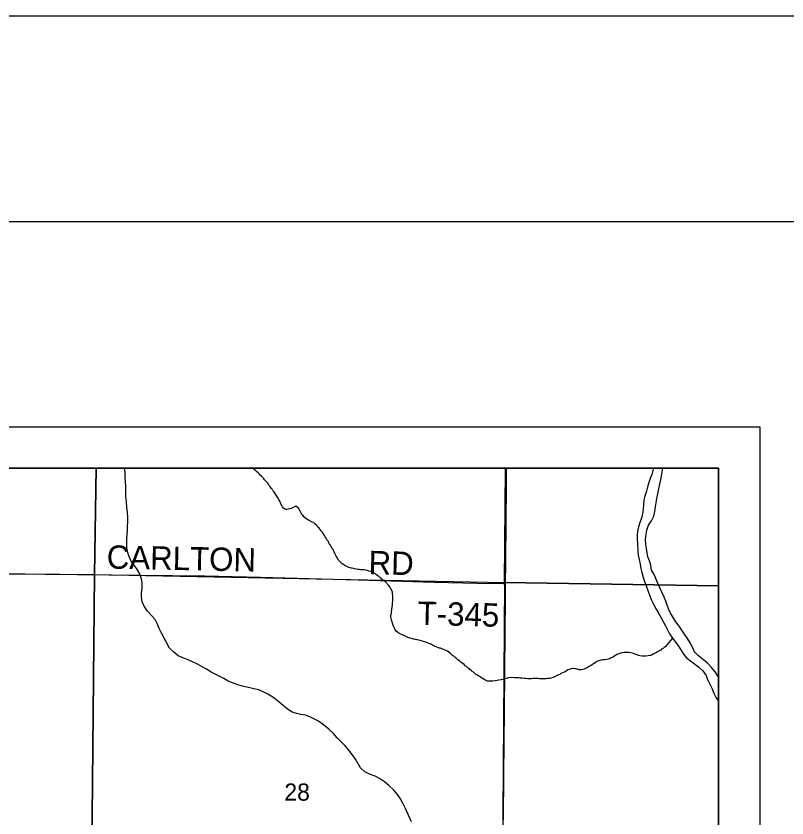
# Model space of a CAD drawing. Extents: x -8.8 to 41.4, y 0 to 34.6.
# Drawn here: x 7.191 to 9.066, y 20.049 to 22 of the extents above; entities that cross this region are included whole.
import ezdxf

# ---------------------------------------------------------------- set-up
doc = ezdxf.new("R2010")
doc.units = 0
for name, color, linetype in [('GM_X_Corporation', 7, 'Continuous'), ('GM_X_Major_Lake', 7, 'Continuous'), ('GM_X_Minor_River', 7, 'Continuous'), ('GM_X_Section_Text', 7, 'Continuous'), ('GM_X_State_Route', 7, 'Continuous'), ('GM_X_Township_Road', 7, 'Continuous'), ('GM_X_Township_Text', 7, 'Continuous'), ('SH_Border', 7, 'Continuous'), ('SH_Cut_Line', 7, 'Continuous'), ('SH_Text', 7, 'Continuous')]:
    doc.layers.add(name, color=color, linetype=linetype)

msp = doc.modelspace()

# ---------------------------------------------------------------- linework, layer by layer
at = {"layer": 'GM_X_Corporation'}
msp.add_lwpolyline([(8.9, 18.5906), (8.9, 20.9), (5.406, 20.9), (5.4056, 20.8652), (5.4051, 20.8193), (5.404, 20.7626), (5.4029, 20.685), (5.4022, 20.6229), (5.4014, 20.5837), (5.4004, 20.5036), (5.3996, 20.4046), (5.3985, 20.3439), (5.3972, 20.2756), (5.3969, 20.2195), (5.3955, 20.1339), (5.3942, 20.0451)], dxfattribs=at)
for points in [[(7.3859, 20.9), (6.3738, 20.9), (6.3701, 20.6506), (7.3817, 20.6407)], [(8.3813, 20.9), (7.3859, 20.9), (7.3817, 20.6407), (8.3787, 20.6214)], [(8.9, 20.6135), (8.9, 20.9), (8.3813, 20.9), (8.3787, 20.6214)], [(6.3701, 20.6506), (7.3817, 20.6407), (7.3719, 19.6303), (6.3565, 19.6406)], [(7.3817, 20.6407), (8.3787, 20.6214), (8.3714, 19.6082), (7.3719, 19.6303)], [(8.9, 19.5991), (8.9, 20.6135), (8.3787, 20.6214), (8.3714, 19.6082)]]:
    msp.add_lwpolyline(points, close=True, dxfattribs=at)
at = {"layer": 'GM_X_Major_Lake'}
for points in [[(8.7418, 20.9), (8.741, 20.8976), (8.7378, 20.8847), (8.7338, 20.8746), (8.7302, 20.8648), (8.7266, 20.8538), (8.7241, 20.8436), (8.7205, 20.8319), (8.7184, 20.8221), (8.717, 20.8111), (8.7165, 20.8004), (8.7144, 20.7887), (8.7123, 20.7785), (8.7079, 20.7679), (8.7047, 20.757), (8.7026, 20.7468), (8.702, 20.7369), (8.7018, 20.7274), (8.7028, 20.7171), (8.7032, 20.6981), (8.7045, 20.6882), (8.7066, 20.6776), (8.7087, 20.6665), (8.7104, 20.6559), (8.7129, 20.6459), (8.7161, 20.6345), (8.72, 20.6242), (8.7236, 20.6135), (8.728, 20.602), (8.732, 20.5909), (8.7367, 20.579), (8.7421, 20.5675), (8.7484, 20.5568), (8.7539, 20.5468), (8.7602, 20.5357), (8.7704, 20.5165), (8.7759, 20.5061), (8.7807, 20.4966), (8.7877, 20.4858), (8.7962, 20.4754), (8.804, 20.4642), (8.8128, 20.4496), (8.8214, 20.4388), (8.8314, 20.4307), (8.8412, 20.424), (8.8509, 20.4166), (8.8617, 20.407), (8.8695, 20.3954), (8.8731, 20.3855), (8.8841, 20.3625), (8.8884, 20.3522), (8.8939, 20.341), (8.9, 20.3331)], [(8.9, 20.3909), (8.899, 20.3926), (8.8917, 20.4041), (8.8827, 20.4145), (8.8734, 20.4246), (8.8634, 20.4331), (8.8514, 20.4432), (8.8413, 20.4525), (8.837, 20.4629), (8.8311, 20.4751), (8.8241, 20.4855), (8.8171, 20.4955), (8.8104, 20.5055), (8.8042, 20.5151), (8.796, 20.5259), (8.789, 20.5367), (8.7831, 20.5467), (8.7787, 20.5562), (8.7751, 20.5665), (8.7715, 20.5761), (8.7672, 20.5861), (8.7624, 20.5964), (8.758, 20.6067), (8.7537, 20.6163), (8.7435, 20.6408), (8.7369, 20.6516), (8.7352, 20.6638), (8.732, 20.6741), (8.728, 20.6844), (8.7263, 20.6939), (8.7242, 20.7042), (8.7228, 20.7141), (8.7223, 20.7263), (8.7233, 20.7388), (8.7254, 20.749), (8.7294, 20.7607), (8.7368, 20.772), (8.7423, 20.7829), (8.7448, 20.7946), (8.7465, 20.8056), (8.7482, 20.8154), (8.7499, 20.8256), (8.7524, 20.8374), (8.7549, 20.8495), (8.757, 20.8608), (8.7592, 20.8726), (8.7621, 20.8854), (8.7646, 20.9)]]:
    msp.add_lwpolyline(points, dxfattribs=at)
at = {"layer": 'GM_X_Minor_River'}
for points in [[(7.5644, 20.4622), (7.5566, 20.4757), (7.5511, 20.4864), (7.5445, 20.4983), (7.539, 20.5094), (7.534, 20.5216), (7.5288, 20.5312), (7.5199, 20.5416), (7.5102, 20.5521), (7.5021, 20.564), (7.4978, 20.5747), (7.4961, 20.5865), (7.4959, 20.5964), (7.4972, 20.6074), (7.4975, 20.6199), (7.4961, 20.6309), (7.4922, 20.6428), (7.4848, 20.6547), (7.477, 20.6647), (7.4696, 20.6751), (7.4649, 20.6866), (7.4617, 20.6969), (7.46, 20.7064), (7.4604, 20.728), (7.4615, 20.7481), (7.4621, 20.7587), (7.4626, 20.7686), (7.4628, 20.7796), (7.4616, 20.7925), (7.4606, 20.8043), (7.4597, 20.818), (7.4581, 20.8306), (7.4579, 20.8431), (7.4578, 20.8564), (7.4569, 20.8667), (7.4559, 20.8788), (7.4558, 20.8895), (7.4548, 20.8997), (7.4547, 20.9)], [(7.8496, 20.7996), (7.8469, 20.7993), (7.8443, 20.8001), (7.8416, 20.8025), (7.839, 20.806), (7.8376, 20.8086), (7.8357, 20.8114), (7.8343, 20.8156), (7.8321, 20.8194), (7.8299, 20.8237), (7.8281, 20.8264), (7.8266, 20.8291), (7.8222, 20.8368), (7.8196, 20.8403), (7.8177, 20.843), (7.8155, 20.8457), (7.8137, 20.8484), (7.8114, 20.8515), (7.8092, 20.8549), (7.8066, 20.858), (7.8048, 20.8608), (7.8033, 20.8631), (7.7981, 20.8685), (7.7955, 20.8716), (7.7925, 20.8751), (7.7902, 20.8778), (7.7876, 20.8802), (7.785, 20.8829), (7.782, 20.8864), (7.7794, 20.8884), (7.7768, 20.8911), (7.7741, 20.893), (7.7711, 20.8958), (7.7681, 20.8981), (7.7653, 20.9)], [(8.1038, 20.5471), (8.1039, 20.5494), (8.1043, 20.5528), (8.1048, 20.5551), (8.1052, 20.5581), (8.1057, 20.5607), (8.1058, 20.5634), (8.1062, 20.5664), (8.1067, 20.5706), (8.1068, 20.5733), (8.1073, 20.5759), (8.1074, 20.5824), (8.1075, 20.585), (8.1072, 20.5904), (8.1069, 20.5934), (8.1063, 20.5987), (8.1027, 20.6064), (8.1001, 20.611), (8.0972, 20.6153), (8.0893, 20.6235), (8.087, 20.6247), (8.0848, 20.6266), (8.0821, 20.6282), (8.0795, 20.6302), (8.0757, 20.6337), (8.0731, 20.636), (8.0709, 20.638), (8.0679, 20.6403), (8.0648, 20.6419), (8.0626, 20.6435), (8.0595, 20.6455), (8.0565, 20.6467), (8.0535, 20.6483), (8.05, 20.6495), (8.047, 20.65), (8.0447, 20.6504), (8.0405, 20.6517), (8.0374, 20.6521), (8.0344, 20.6522), (8.0313, 20.6526), (8.0286, 20.6527), (8.0255, 20.6532), (8.0225, 20.6532), (8.0148, 20.6549), (8.0114, 20.6558), (8.0087, 20.6566), (8.006, 20.6567), (7.9999, 20.6584), (7.9977, 20.6595), (7.9939, 20.6612), (7.9905, 20.6631), (7.9882, 20.6643), (7.9844, 20.6671), (7.9821, 20.6683), (7.9807, 20.6706), (7.9754, 20.6761), (7.971, 20.683), (7.9699, 20.6853), (7.9684, 20.6876), (7.9674, 20.6903), (7.9659, 20.693), (7.9648, 20.6953), (7.9619, 20.7019), (7.9593, 20.705), (7.9578, 20.7077), (7.9549, 20.7134), (7.9527, 20.7158), (7.9516, 20.7188), (7.9498, 20.7219), (7.9468, 20.7258), (7.9453, 20.7292), (7.9424, 20.7331), (7.9398, 20.7381), (7.9376, 20.7408), (7.9354, 20.7447), (7.9328, 20.747), (7.9309, 20.7505), (7.9279, 20.754), (7.9253, 20.7563), (7.9231, 20.7594), (7.9178, 20.7641), (7.9141, 20.7672), (7.9114, 20.7688), (7.9054, 20.772), (7.902, 20.7736), (7.8982, 20.7756), (7.8959, 20.7772), (7.8906, 20.7811), (7.8881, 20.7854), (7.8862, 20.7877), (7.8847, 20.79), (7.8822, 20.7954), (7.8778, 20.8023), (7.8747, 20.8047), (7.8717, 20.8074), (7.8663, 20.8049), (7.8628, 20.8031), (7.8605, 20.802), (7.8566, 20.8006), (7.8527, 20.7999), (7.8496, 20.7996)], [(8.4223, 20.3884), (8.4196, 20.3888), (8.4173, 20.3889), (8.4143, 20.3894), (8.4077, 20.3895), (8.4035, 20.39), (8.3966, 20.3902), (8.3889, 20.3896), (8.3866, 20.3889), (8.3827, 20.3882), (8.3785, 20.3872), (8.3746, 20.3858), (8.3707, 20.3851), (8.3646, 20.3837), (8.3611, 20.3831), (8.3561, 20.3824), (8.3507, 20.3814), (8.348, 20.3811), (8.3403, 20.3813), (8.3376, 20.3817), (8.3346, 20.383), (8.3319, 20.3842), (8.3285, 20.3862), (8.3243, 20.3885), (8.3206, 20.3913), (8.3179, 20.3925), (8.3141, 20.3952), (8.3119, 20.3968), (8.3096, 20.398), (8.3062, 20.4011), (8.304, 20.4031), (8.3006, 20.4051), (8.298, 20.4078), (8.2946, 20.4102), (8.2919, 20.4129), (8.2893, 20.4141), (8.2871, 20.4172), (8.2836, 20.4188), (8.281, 20.4219), (8.2773, 20.4247), (8.2739, 20.4266), (8.2716, 20.4282), (8.2694, 20.4313), (8.2652, 20.4333), (8.2634, 20.436), (8.2603, 20.438), (8.2581, 20.4403), (8.2555, 20.4427), (8.2528, 20.4443), (8.2491, 20.4474), (8.2468, 20.4493), (8.24, 20.4541), (8.2359, 20.4565), (8.2317, 20.4585), (8.2267, 20.4605), (8.2237, 20.4617), (8.2206, 20.4622), (8.2184, 20.463), (8.2142, 20.4646), (8.21, 20.4658), (8.2073, 20.4674), (8.2035, 20.469), (8.2013, 20.4706), (8.1979, 20.4722), (8.1952, 20.473), (8.1903, 20.4754), (8.1876, 20.4763), (8.1834, 20.4775), (8.1792, 20.4791), (8.1739, 20.4808), (8.1704, 20.4816), (8.1666, 20.4821), (8.1643, 20.4825), (8.1613, 20.483), (8.1578, 20.4838), (8.1552, 20.4847), (8.1529, 20.4851), (8.149, 20.4863), (8.1468, 20.4872), (8.1437, 20.488), (8.1403, 20.4896), (8.1357, 20.4916), (8.1323, 20.4936), (8.1266, 20.4956), (8.1228, 20.4976), (8.1191, 20.5004), (8.1157, 20.5031), (8.1138, 20.5054), (8.1124, 20.5078), (8.1113, 20.5108), (8.1091, 20.5151), (8.108, 20.5177), (8.1073, 20.5204), (8.1062, 20.5227), (8.1055, 20.5262), (8.1045, 20.53), (8.1031, 20.5346), (8.1028, 20.5384), (8.1029, 20.5422), (8.103, 20.5445), (8.1038, 20.5471)], [(8.7877, 20.4858), (8.7701, 20.465), (8.7678, 20.4631), (8.7647, 20.4613), (8.7611, 20.4591), (8.7592, 20.4569), (8.7568, 20.4562), (8.7545, 20.4547), (8.7514, 20.4529), (8.749, 20.451), (8.7455, 20.4496), (8.7432, 20.4478), (8.7408, 20.4471), (8.7369, 20.4449), (8.7342, 20.4442), (8.7319, 20.4439), (8.7288, 20.4432), (8.7227, 20.4426), (8.7184, 20.4423), (8.7146, 20.4424), (8.7085, 20.4433), (8.705, 20.4441), (8.7016, 20.4458), (8.6986, 20.4466), (8.6951, 20.4478), (8.6925, 20.449), (8.6864, 20.4507), (8.6818, 20.4512), (8.6726, 20.4514), (8.6691, 20.4511), (8.6664, 20.4508), (8.6641, 20.4505), (8.6618, 20.4494), (8.6548, 20.4473), (8.6525, 20.4462), (8.6446, 20.4411), (8.6423, 20.4396), (8.6396, 20.4382), (8.6372, 20.4371), (8.6341, 20.436), (8.631, 20.4353), (8.6279, 20.4343), (8.6225, 20.4336), (8.6202, 20.4333), (8.6179, 20.4334), (8.6133, 20.4327), (8.611, 20.432), (8.6083, 20.4313), (8.604, 20.4292), (8.6016, 20.4277), (8.5993, 20.4258), (8.5957, 20.4233), (8.5934, 20.4222), (8.5895, 20.4196), (8.5848, 20.4171), (8.5801, 20.4142), (8.5774, 20.4131), (8.5728, 20.4109), (8.5693, 20.4099), (8.5658, 20.4092), (8.5608, 20.4093), (8.5585, 20.4097), (8.5555, 20.4106), (8.5532, 20.4114), (8.5509, 20.4118), (8.5467, 20.4123), (8.5444, 20.4124), (8.5413, 20.4113), (8.5386, 20.411), (8.5362, 20.4095), (8.5335, 20.4088), (8.53, 20.407), (8.5265, 20.4045), (8.5242, 20.4038), (8.5203, 20.4016), (8.516, 20.3998), (8.5136, 20.3979), (8.5101, 20.3969), (8.5074, 20.3954), (8.5043, 20.3936), (8.4973, 20.3904), (8.4919, 20.3886), (8.4895, 20.3883), (8.4872, 20.3876), (8.4845, 20.3876), (8.4803, 20.3874), (8.478, 20.387), (8.4726, 20.3872), (8.4699, 20.3868), (8.4661, 20.3873), (8.4638, 20.3874), (8.4611, 20.3878), (8.4584, 20.3879), (8.4561, 20.3876), (8.4484, 20.3878), (8.4446, 20.3875), (8.4376, 20.3869), (8.4346, 20.387), (8.4307, 20.3878), (8.4269, 20.3883), (8.4223, 20.3884)], [(8.1526, 20.039), (8.1479, 20.0501), (8.1384, 20.0715), (8.1326, 20.0834), (8.126, 20.0949), (8.119, 20.106), (8.1101, 20.1165), (8.0977, 20.1277), (8.0869, 20.1366), (8.0749, 20.1448), (8.064, 20.1503), (8.0504, 20.1548), (8.0392, 20.1607), (8.0287, 20.1707), (8.0166, 20.1919), (8.0088, 20.2034), (8.0007, 20.2138), (7.9925, 20.2234), (7.9813, 20.2335), (7.972, 20.2436), (7.9627, 20.254), (7.9519, 20.2648), (7.9384, 20.2753), (7.9268, 20.2839), (7.9171, 20.2894), (7.9073, 20.2941), (7.8949, 20.2985), (7.8835, 20.3006), (7.8737, 20.3027), (7.8628, 20.3063), (7.8511, 20.313), (7.8354, 20.3262), (7.8257, 20.3347), (7.8152, 20.3425), (7.8032, 20.35), (7.7923, 20.3555), (7.781, 20.3602), (7.7693, 20.3627), (7.7595, 20.3652), (7.7485, 20.3677), (7.7387, 20.3701), (7.7281, 20.373), (7.7172, 20.3774), (7.7071, 20.3817), (7.6965, 20.388), (7.677, 20.3975), (7.6653, 20.4034), (7.6537, 20.4105), (7.6436, 20.416), (7.6319, 20.4226), (7.6184, 20.4293), (7.6071, 20.4345), (7.595, 20.4389), (7.5849, 20.4432), (7.5744, 20.4518), (7.5644, 20.4622)]]:
    msp.add_lwpolyline(points, dxfattribs=at)
at = {"layer": 'GM_X_State_Route'}
msp.add_lwpolyline([(8.3766, 20.0439), (8.3774, 20.1544), (8.3791, 20.3104), (8.3799, 20.403), (8.3804, 20.5011), (8.3813, 20.5825), (8.3816, 20.6192), (8.382, 20.6695), (8.3834, 20.7745), (8.3836, 20.8509), (8.3842, 20.9)], dxfattribs=at)
at = {"layer": 'GM_X_Township_Road'}
msp.add_lwpolyline([(7.1293, 20.6429), (7.2632, 20.6418), (7.4924, 20.6398), (7.649, 20.6376), (7.7856, 20.6346), (8.0234, 20.6281), (8.2091, 20.6223), (8.3116, 20.6203), (8.3755, 20.6194), (8.3816, 20.6192)], dxfattribs=at)
at = {"layer": 'SH_Border'}
for p, q in [((2, 21), (9, 21)), ((9, 21), (9, 14)), ((2.1, 20.9), (8.9, 20.9)), ((8.9, 20.9), (8.9, 14.1))]:
    msp.add_line(p, q, dxfattribs=at)
at = {"layer": 'SH_Cut_Line'}
msp.add_lwpolyline([(1.5, 21.5), (33.5, 21.5), (33.5, 0.5), (1.5, 0.5)], close=True, dxfattribs=at)
at = {"layer": 'SH_Text'}
msp.add_lwpolyline([(0, 0), (34, 0), (34, 22), (0, 22)], close=True, dxfattribs=at)

# ---------------------------------------------------------------- texts
at = {"layer": 'GM_X_Section_Text'}
for s, rotation, p in [('CARLTON', 358.8363, (7.4109, 20.6555)), ('RD', 358.5194, (8.0477, 20.6421)), ('T-345', 358.5957, (8.1672, 20.5187))]:
    msp.add_text(s, height=0.05682, rotation=rotation, dxfattribs=at).set_placement(p)
at = {"layer": 'GM_X_Township_Text'}
msp.add_text('28', height=0.04186, rotation=0, dxfattribs=at).set_placement((7.8434, 20.0907))

doc.saveas('drawing.dxf')
